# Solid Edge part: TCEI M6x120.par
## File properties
Subject: Vite TCEI M6x120
Template: RBuno.par
Last saved by: f_grande
Revision: 16
Application: Solid Edge
Codice: Codice
Indice rev.: Rev.
Data rev.: Data rev.
Firma rev.: Firma rev.
Descrizione rev.: Descrizione rev.
Densità: 7860,000 kg/m^3
Precisione: 0,99
Tipo di contenuto documento: 0
Material: Classe 8.8
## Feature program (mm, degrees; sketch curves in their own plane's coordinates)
sketch for "unnamed Protrusion 1" plane through (0, 0, 0) normal (0, 0, 1) x-axis (1, 0, 0)
extrude "unnamed Protrusion 1" add finite 6 along +normal
sketch for "ExtrudedProtrusion_3" plane through (0, 0, 0) normal (0, 0, -1) x-axis (-1, 0, 0)
extrude "ExtrudedProtrusion_3" add finite 120 along +normal
sketch for "ExtrudedProtrusion_4" plane through (0, 0, -120) normal (0, 0, -1) x-axis (0, 1, 0)
extrude "ExtrudedProtrusion_4" add finite 18 along -normal
sketch for "ExtrudedCutout_1" plane through (0, 0, 6) normal (0, 0, 1) x-axis (0, 1, 0)
  line (-2.5, 1.4434) -> (-2.5, -1.4434)
  line (-2.5, -1.4434) -> (0, -2.8868)
  line (0, -2.8868) -> (2.5, -1.4434)
  line (2.5, -1.4434) -> (2.5, 1.4434)
  line (2.5, 1.4434) -> (0, 2.8868)
  line (0, 2.8868) -> (-2.5, 1.4434)
extrude "ExtrudedCutout_1" cut finite 4 along -normal
fillet "Rotondo_2" radius 0.5
chamfer "Chamfer_1" setback 0.5
thread "unnamed Thread 1"
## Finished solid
Body 1: solid body, 16 faces, 26 edges, 12 vertices.
  Faces by surface: plane 11, cylinder 3, cone 1, torus 1
  Edges by curve: line 18, circle 8
Bounding box of the edges (mm; curved faces can reach further): 10.000 x 10.000 x 126.000, from (-5, -5, -120) to (5, 5, 6).
Cylindrical faces by radius (mm): R2.95 x1, R3 x1, R5 x1
Conical faces (half-angle, radius in mm at the cone's reference point): 45 deg R3 x1
Toroidal faces (ring radius, tube radius in mm): R4.5 r0.5 x1
Planar faces by outward normal: +y 1, +z 3, -y 1, -z 2, oblique 4
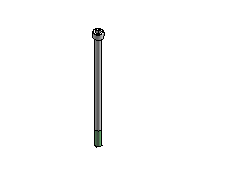
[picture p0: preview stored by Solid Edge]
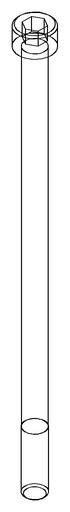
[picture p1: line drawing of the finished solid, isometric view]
